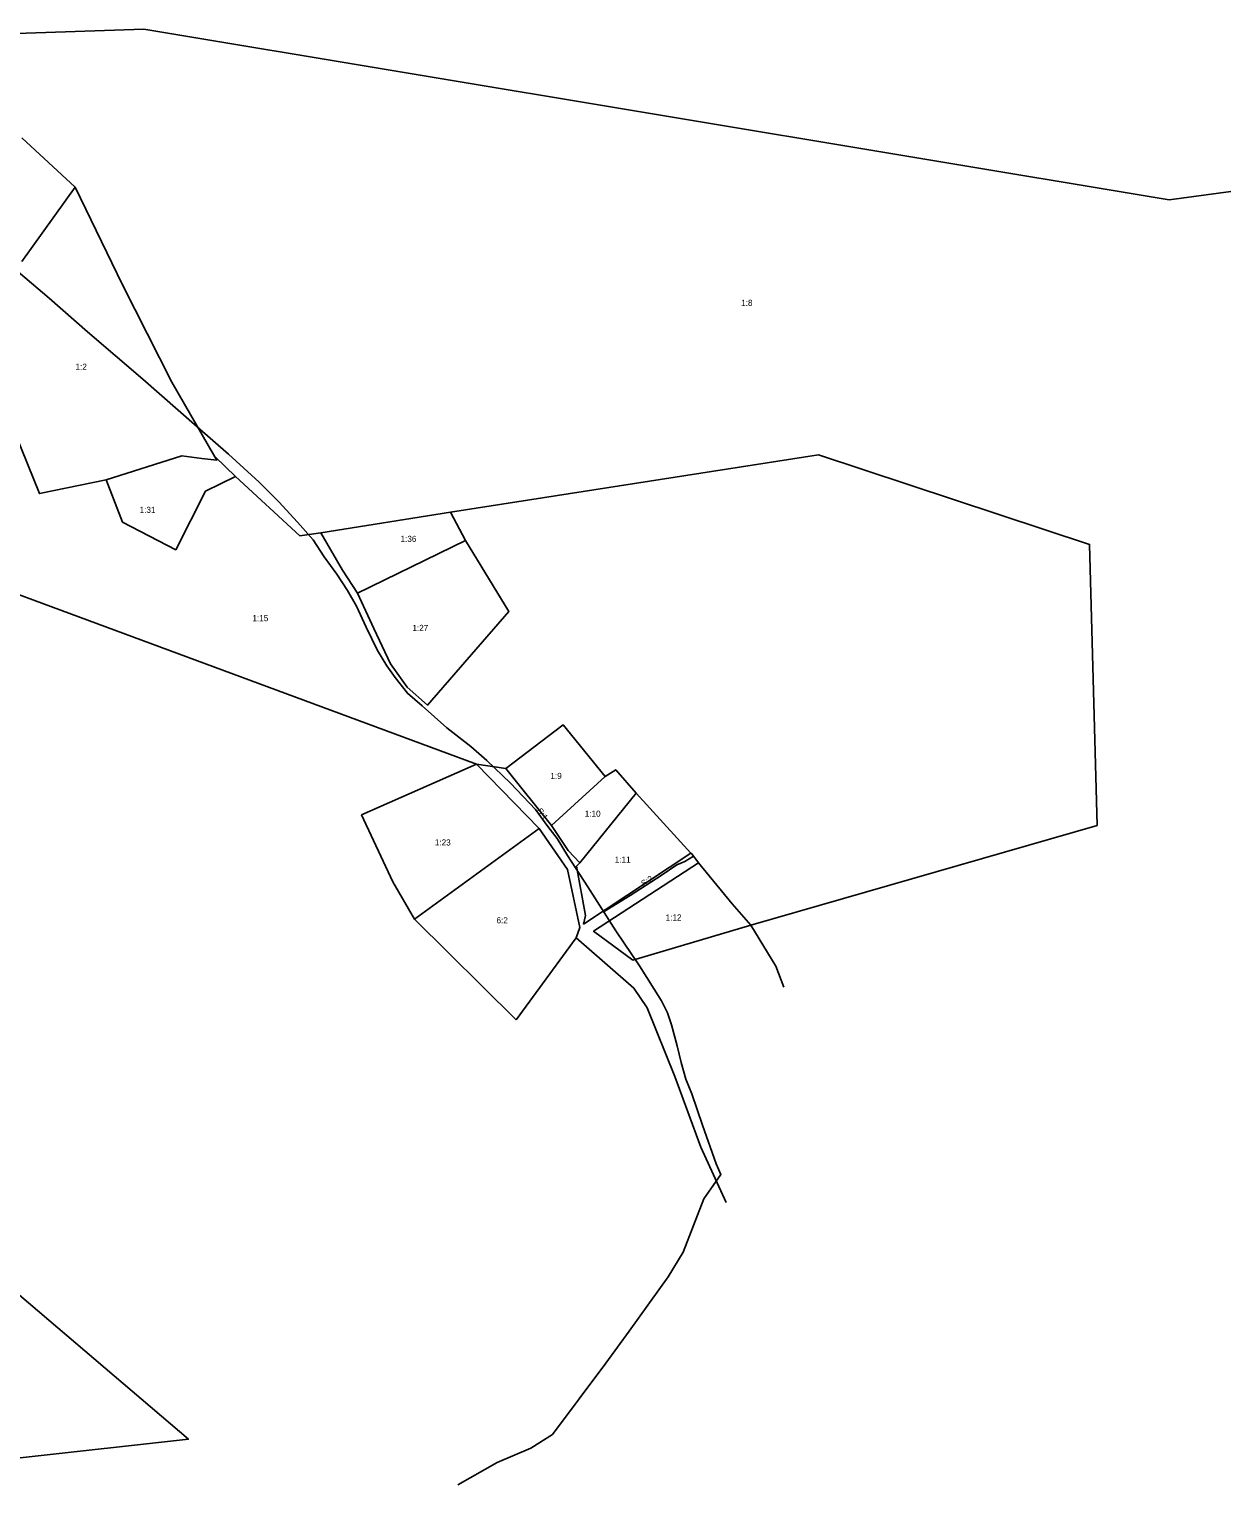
# Model space of a CAD drawing. Extents: x 140824 to 143748, y 6547319 to 6550906.
# Drawn here: x 142666 to 143355, y 6547319 to 6548160 of the extents above; entities that cross this region are included whole.
import ezdxf

# ---------------------------------------------------------------- set-up
doc = ezdxf.new("R2010")
doc.units = 0
for name, color, linetype in [('FAST Fastighetsgräns', 7, 'Continuous'), ('FAST Mittlinjeredovisad samfällighet', 7, 'Continuous'), ('FAST Registernummer för fastighet', 7, 'Continuous'), ('FAST Registernummer för mittlinjeredovisad samfällighet', 7, 'Continuous'), ('FAST Traktgräns', 7, 'Continuous')]:
    doc.layers.add(name, color=color, linetype=linetype)

msp = doc.modelspace()

# ---------------------------------------------------------------- linework, layer by layer
at = {"layer": 'FAST Fastighetsgräns'}
for p, q in [((142661.71, 6548097.46), (142692.38, 6548069.07)), ((142692.38, 6548069.07), (142661.74, 6548026.47)), ((142753.62, 6547915.01), (142710.21, 6547901.25)), ((142765.09, 6547913.53), (142753.62, 6547915.01)), ((142833.35, 6547870.73), (142907.7, 6547882.61)), ((142907.7, 6547882.61), (142916.24, 6547866.37)), ((142854.35, 6547836.13), (142916.24, 6547866.37)), ((142965.51, 6547702.94), (142996.33, 6547731.07)), ((143014.06, 6547721.56), (142981.9, 6547681.47)), ((143014.06, 6547721.56), (143045.58, 6547687.15)), ((142958.46, 6547701.14), (142886.94, 6547649.18)), ((143012.28, 6547625.6), (143079.87, 6547645.67)), ((142979.65, 6547638.53), (142945.29, 6547591.51))]:
    msp.add_line(p, q, dxfattribs=at)
for points in [[(142692.38, 6548069.07), (142719.45, 6548013), (142747.83, 6547957.18), (142772.4, 6547914.44)], [(142710.21, 6547901.25), (142671.97, 6547893.34), (142629.96, 6547996.54), (142659.74, 6548023.7)], [(142765.09, 6547913.53), (142773.54, 6547912.44), (142772.4, 6547914.44)], [(142772.4, 6547914.44), (142772.6, 6547914.47), (142784.28, 6547903.13)], [(142907.7, 6547882.61), (143118.68, 6547915.59), (143274.21, 6547864.14), (143278.55, 6547703)], [(142710.21, 6547901.25), (142719.51, 6547876.98), (142750.06, 6547861.11), (142767.03, 6547894.63), (142784.28, 6547903.13)], [(142784.28, 6547903.13), (142821.3, 6547869.07), (142833.35, 6547870.73)], [(142854.35, 6547836.13), (142845.73, 6547849.38), (142833.35, 6547870.73)], [(142916.24, 6547866.37), (142941.06, 6547825.65), (142894.5, 6547771.98), (142882.8, 6547782.31), (142873.18, 6547795.59), (142863.76, 6547815.86), (142854.35, 6547836.13)], [(142939.46, 6547735.69), (142972.19, 6547760.76), (142996.33, 6547731.07)], [(142996.33, 6547731.07), (143002.45, 6547734.89), (143014.06, 6547721.56)], [(143049.91, 6547681.53), (143069.23, 6547657.98), (143079.87, 6547645.67)]]:
    msp.add_lwpolyline(points, dxfattribs=at)
at = {"layer": 'FAST Mittlinjeredovisad samfällighet'}
for points in [[(142581.63, 6548147.56), (142585.08, 6548139.58), (142596.03, 6548108.56), (142603.35, 6548087.62), (142611.48, 6548070.4), (142616.66, 6548061.74), (142621.56, 6548054.74), (142632.99, 6548043.03), (142677.52, 6548005.37), (142699.43, 6547986.09), (142731.1, 6547958.97), (142762.42, 6547931.66)], [(142762.42, 6547931.66), (142780.32, 6547915.97), (142797.82, 6547899.81), (142809.1, 6547888.51), (142819.9, 6547876.93), (142828.79, 6547866.71), (142835.15, 6547857.1), (142842.52, 6547847.09), (142848.49, 6547837.79), (142853.69, 6547828.76), (142859.22, 6547816.66), (142865.82, 6547803.37), (142871.04, 6547794.45), (142876, 6547787.81), (142882.92, 6547778.75), (142891.41, 6547771.61), (142905.47, 6547758.87), (142919.23, 6547748.24), (142928.56, 6547740.2), (142941.99, 6547727.23), (142956.4, 6547712.14), (142963.44, 6547702.43), (142968.78, 6547695.56), (142974.84, 6547685.65), (142986.47, 6547667.76), (143002.47, 6547642.42), (143015.99, 6547622.41), (143028.64, 6547602.34), (143032.14, 6547595.53), (143034.4, 6547588.5), (143037.61, 6547576.45), (143039.99, 6547567.03), (143042.71, 6547557.45), (143046.02, 6547549.04), (143052.27, 6547531.06), (143060.07, 6547508.86), (143062.65, 6547502.74), (143052.87, 6547488.77), (143041.12, 6547458.13), (143032.49, 6547443.98), (143010.13, 6547412.94), (142996.8, 6547394.47), (142966.2, 6547353.6), (142953.64, 6547345.74), (142934.4, 6547337.47), (142911.89, 6547324.78)], [(142995.69, 6547653.69), (143010.69, 6547662.78), (143028.56, 6547674.28), (143037.38, 6547680.41), (143042, 6547682.33), (143047, 6547685.37)]]:
    msp.add_lwpolyline(points, dxfattribs=at)
at = {"layer": 'FAST Traktgräns'}
for p, q in [((142922.53, 6547738.17), (142357.53, 6547947.34)), ((142958.46, 6547701.14), (142922.53, 6547738.17)), ((142922.53, 6547738.17), (142939.46, 6547735.69)), ((142939.46, 6547735.69), (142965.51, 6547702.94)), ((143079.87, 6547645.67), (143278.55, 6547703)), ((143045.58, 6547687.15), (142983.88, 6547646.41)), ((142886.94, 6547649.18), (142945.29, 6547591.51))]:
    msp.add_line(p, q, dxfattribs=at)
for points in [[(143355.14, 6548066.67), (143319.95, 6548061.86), (142731.69, 6548159.66), (142613.33, 6548155.79)], [(142922.53, 6547738.17), (142856.67, 6547709.05), (142874.56, 6547670.53), (142886.94, 6547649.18)], [(142981.9, 6547681.47), (142975.1, 6547688.67), (142965.51, 6547702.94)], [(142979.65, 6547638.53), (142981.82, 6547644.47), (142974.78, 6547677.67), (142958.46, 6547701.14)], [(143045.58, 6547687.15), (143046.05, 6547686.64), (143049.91, 6547681.53)], [(142983.88, 6547646.41), (142985.03, 6547651.38), (142979.84, 6547679.53), (142981.9, 6547681.47)], [(143012.28, 6547625.6), (142989.76, 6547642.24), (143049.91, 6547681.53)], [(143079.87, 6547645.67), (143094.2, 6547622.26), (143098.85, 6547610.13)], [(142418.59, 6547639.53), (142757.29, 6547350.84), (142469.32, 6547319.05)], [(143065.83, 6547486.63), (143051.19, 6547518.48), (143036.36, 6547558.91), (143020.5, 6547598.36), (143012.82, 6547609.58), (142996.24, 6547624.06), (142979.65, 6547638.53)]]:
    msp.add_lwpolyline(points, dxfattribs=at)

# ---------------------------------------------------------------- texts
at = {"layer": 'FAST Registernummer för fastighet'}
for s, p in [('1:8', (143074.36, 6548001)), ('1:2', (142692.56, 6547964.37)), ('1:31', (142729.32, 6547882.26)), ('1:36', (142878.99, 6547865.61)), ('1:15', (142794.02, 6547820.14)), ('1:27', (142885.79, 6547814.52)), ('1:9', (142964.94, 6547729.64)), ('1:10', (142984.64, 6547707.99)), ('1:23', (142898.65, 6547691.47)), ('1:11', (143001.84, 6547681.64)), ('6:2', (142934.03, 6547646.82)), ('1:12', (143031.06, 6547648.43))]:
    msp.add_text(s, height=3.5, dxfattribs=at).set_placement(p)
at = {"layer": 'FAST Registernummer för mittlinjeredovisad samfällighet'}
for s, rotation, p in [('S:1', 305.752, (142956.94, 6547711.4)), ('S:2', 32.659, (143018.35, 6547667.72))]:
    msp.add_text(s, height=3.5, rotation=rotation, dxfattribs=at).set_placement(p)

doc.saveas('drawing.dxf')
